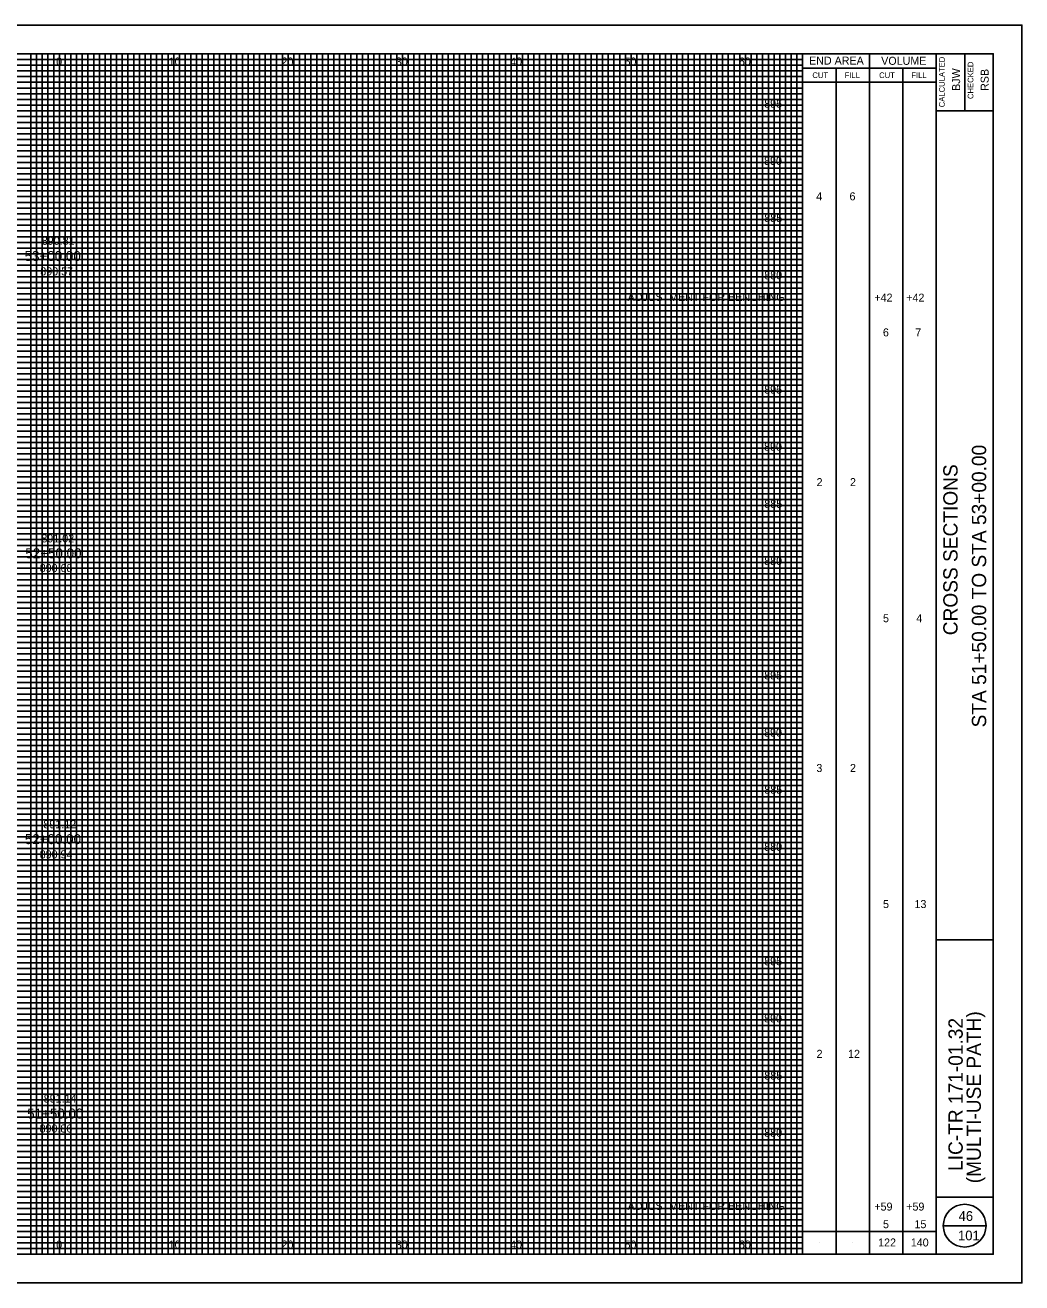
# Model space of a CAD drawing. Extents: x -10 to 160, y -2 to 2522.
# Drawn here: x 72.8 to 160, y 2067.5 to 2177.5 of the extents above; entities that cross this region are included whole.
import ezdxf

# ---------------------------------------------------------------- set-up
doc = ezdxf.new("R2010")
doc.units = 0
for name, color, linetype in [('GK_Cells', 7, 'Continuous'), ('GK_Patterns', 7, 'Continuous'), ('TX_P_10', 7, 'Continuous'), ('TX_X_10', 7, 'Continuous'), ('XS_P_Finished_Grade_Seeded', 7, 'Continuous'), ('XS_P_Pavt_Surface', 7, 'Continuous'), ('XS_P_Subgrade', 7, 'Continuous'), ('XS_X_Ground_Line', 7, 'Continuous')]:
    doc.layers.add(name, color=color, linetype=linetype)

msp = doc.modelspace()

# ---------------------------------------------------------------- linework, layer by layer
at = {"layer": 'GK_Cells'}
msp.add_lwpolyline([(-10, 2067.5), (160, 2067.5), (160, 2177.5), (-10, 2177.5)], close=True, dxfattribs=at)
at = {"layer": 'TX_P_10'}
for p, q in [((140.83, 2070), (140.83, 2175)), ((146.67, 2070), (146.67, 2175)), ((140.83, 2173.75), (152.5, 2173.75)), ((143.75, 2070), (143.75, 2173.75)), ((149.58, 2070), (149.58, 2173.75)), ((140.83, 2172.5), (152.5, 2172.5)), ((153.12, 2072.5), (156.88, 2072.5)), ((140.83, 2072), (152.5, 2072)), ((142.29, 2071), (142.29, 2071)), ((145.21, 2071), (145.21, 2071)), ((148.12, 2071), (148.12, 2071)), ((151.04, 2071), (151.04, 2071))]:
    msp.add_line(p, q, dxfattribs=at)
msp.add_circle((155, 2072.5), 1.87, dxfattribs=at)
at = {"layer": 'TX_X_10'}
for p, q in [((75.83, 2070), (75.83, 2175)), ((80.83, 2070), (80.83, 2175)), ((85.83, 2070), (85.83, 2175)), ((90.83, 2070), (90.83, 2175)), ((95.83, 2070), (95.83, 2175)), ((100.83, 2070), (100.83, 2175)), ((105.83, 2070), (105.83, 2175)), ((110.83, 2070), (110.83, 2175)), ((115.83, 2070), (115.83, 2175)), ((120.83, 2070), (120.83, 2175)), ((125.83, 2070), (125.83, 2175)), ((130.83, 2070), (130.83, 2175)), ((135.83, 2070), (135.83, 2175)), ((5.83, 2170), (140.83, 2170)), ((5.83, 2165), (140.83, 2165)), ((5.83, 2160), (140.83, 2160)), ((5.83, 2155), (140.83, 2155)), ((5.83, 2150), (140.83, 2150)), ((5.83, 2145), (140.83, 2145)), ((5.83, 2140), (140.83, 2140)), ((5.83, 2135), (140.83, 2135)), ((5.83, 2130), (140.83, 2130)), ((5.83, 2125), (140.83, 2125)), ((5.83, 2120), (140.83, 2120)), ((5.83, 2115), (140.83, 2115)), ((5.83, 2110), (140.83, 2110)), ((5.83, 2105), (140.83, 2105)), ((5.83, 2100), (140.83, 2100)), ((5.83, 2095), (140.83, 2095)), ((5.83, 2090), (140.83, 2090)), ((5.83, 2085), (140.83, 2085)), ((5.83, 2080), (140.83, 2080)), ((5.83, 2075), (140.83, 2075))]:
    msp.add_line(p, q, dxfattribs=at)
at = {"layer": 'XS_P_Pavt_Surface'}
for p, q in [((152.5, 2070), (152.5, 2175)), ((155, 2175), (155, 2170)), ((152.5, 2170), (157.5, 2170)), ((152.5, 2097.5), (157.5, 2097.5)), ((152.5, 2075), (157.5, 2075))]:
    msp.add_line(p, q, dxfattribs=at)
msp.add_lwpolyline([(0, 2175), (157.5, 2175), (157.5, 2070), (0, 2070)], close=True, dxfattribs=at)
at = {"layer": 'XS_X_Ground_Line'}
for p, q in [((73.33, 2070), (73.33, 2175)), ((73.83, 2070), (73.83, 2175)), ((74.33, 2070), (74.33, 2175)), ((74.83, 2070), (74.83, 2175)), ((75.33, 2070), (75.33, 2175)), ((76.33, 2070), (76.33, 2175)), ((76.83, 2070), (76.83, 2175)), ((77.33, 2070), (77.33, 2175)), ((77.83, 2070), (77.83, 2175)), ((78.33, 2070), (78.33, 2175)), ((78.83, 2070), (78.83, 2175)), ((79.33, 2070), (79.33, 2175)), ((79.83, 2070), (79.83, 2175)), ((80.33, 2070), (80.33, 2175)), ((81.33, 2070), (81.33, 2175)), ((81.83, 2070), (81.83, 2175)), ((82.33, 2070), (82.33, 2175)), ((82.83, 2070), (82.83, 2175)), ((83.33, 2070), (83.33, 2175)), ((83.83, 2070), (83.83, 2175)), ((84.33, 2070), (84.33, 2175)), ((84.83, 2070), (84.83, 2175)), ((85.33, 2070), (85.33, 2175)), ((86.33, 2070), (86.33, 2175)), ((86.83, 2070), (86.83, 2175)), ((87.33, 2070), (87.33, 2175)), ((87.83, 2070), (87.83, 2175)), ((88.33, 2070), (88.33, 2175)), ((88.83, 2070), (88.83, 2175)), ((89.33, 2070), (89.33, 2175)), ((89.83, 2070), (89.83, 2175)), ((90.33, 2070), (90.33, 2175)), ((91.33, 2070), (91.33, 2175)), ((91.83, 2070), (91.83, 2175)), ((92.33, 2070), (92.33, 2175)), ((92.83, 2070), (92.83, 2175)), ((93.33, 2070), (93.33, 2175)), ((93.83, 2070), (93.83, 2175)), ((94.33, 2070), (94.33, 2175)), ((94.83, 2070), (94.83, 2175)), ((95.33, 2070), (95.33, 2175)), ((96.33, 2070), (96.33, 2175)), ((96.83, 2070), (96.83, 2175)), ((97.33, 2070), (97.33, 2175)), ((97.83, 2070), (97.83, 2175)), ((98.33, 2070), (98.33, 2175)), ((98.83, 2070), (98.83, 2175)), ((99.33, 2070), (99.33, 2175)), ((99.83, 2070), (99.83, 2175)), ((100.33, 2070), (100.33, 2175)), ((101.33, 2070), (101.33, 2175)), ((101.83, 2070), (101.83, 2175)), ((102.33, 2070), (102.33, 2175)), ((102.83, 2070), (102.83, 2175)), ((103.33, 2070), (103.33, 2175)), ((103.83, 2070), (103.83, 2175)), ((104.33, 2070), (104.33, 2175)), ((104.83, 2070), (104.83, 2175)), ((105.33, 2070), (105.33, 2175)), ((106.33, 2070), (106.33, 2175)), ((106.83, 2070), (106.83, 2175)), ((107.33, 2070), (107.33, 2175)), ((107.83, 2070), (107.83, 2175)), ((108.33, 2070), (108.33, 2175)), ((108.83, 2070), (108.83, 2175)), ((109.33, 2070), (109.33, 2175)), ((109.83, 2070), (109.83, 2175)), ((110.33, 2070), (110.33, 2175)), ((111.33, 2070), (111.33, 2175)), ((111.83, 2070), (111.83, 2175)), ((112.33, 2070), (112.33, 2175)), ((112.83, 2070), (112.83, 2175)), ((113.33, 2070), (113.33, 2175)), ((113.83, 2070), (113.83, 2175)), ((114.33, 2070), (114.33, 2175)), ((114.83, 2070), (114.83, 2175)), ((115.33, 2070), (115.33, 2175)), ((116.33, 2070), (116.33, 2175)), ((116.83, 2070), (116.83, 2175)), ((117.33, 2070), (117.33, 2175)), ((117.83, 2070), (117.83, 2175)), ((118.33, 2070), (118.33, 2175)), ((118.83, 2070), (118.83, 2175)), ((119.33, 2070), (119.33, 2175)), ((119.83, 2070), (119.83, 2175)), ((120.33, 2070), (120.33, 2175)), ((121.33, 2070), (121.33, 2175)), ((121.83, 2070), (121.83, 2175)), ((122.33, 2070), (122.33, 2175)), ((122.83, 2070), (122.83, 2175)), ((123.33, 2070), (123.33, 2175)), ((123.83, 2070), (123.83, 2175)), ((124.33, 2070), (124.33, 2175)), ((124.83, 2070), (124.83, 2175)), ((125.33, 2070), (125.33, 2175)), ((126.33, 2070), (126.33, 2175)), ((126.83, 2070), (126.83, 2175)), ((127.33, 2070), (127.33, 2175)), ((127.83, 2070), (127.83, 2175)), ((128.33, 2070), (128.33, 2175)), ((128.83, 2070), (128.83, 2175)), ((129.33, 2070), (129.33, 2175)), ((129.83, 2070), (129.83, 2175)), ((130.33, 2070), (130.33, 2175)), ((131.33, 2070), (131.33, 2175)), ((131.83, 2070), (131.83, 2175)), ((132.33, 2070), (132.33, 2175)), ((132.83, 2070), (132.83, 2175)), ((133.33, 2070), (133.33, 2175)), ((133.83, 2070), (133.83, 2175)), ((134.33, 2070), (134.33, 2175)), ((134.83, 2070), (134.83, 2175)), ((135.33, 2070), (135.33, 2175)), ((136.33, 2070), (136.33, 2175)), ((136.83, 2070), (136.83, 2175)), ((137.33, 2070), (137.33, 2175)), ((137.83, 2070), (137.83, 2175)), ((138.33, 2070), (138.33, 2175)), ((138.83, 2070), (138.83, 2175)), ((139.33, 2070), (139.33, 2175)), ((139.83, 2070), (139.83, 2175)), ((140.33, 2070), (140.33, 2175)), ((5.83, 2174.5), (140.83, 2174.5)), ((5.83, 2174), (140.83, 2174)), ((5.83, 2173.5), (140.83, 2173.5)), ((5.83, 2173), (140.83, 2173)), ((5.83, 2172.5), (140.83, 2172.5)), ((5.83, 2172), (140.83, 2172)), ((5.83, 2171.5), (140.83, 2171.5)), ((5.83, 2171), (140.83, 2171)), ((5.83, 2170.5), (140.83, 2170.5)), ((5.83, 2169.5), (140.83, 2169.5)), ((5.83, 2169), (140.83, 2169)), ((5.83, 2168.5), (140.83, 2168.5)), ((5.83, 2168), (140.83, 2168)), ((5.83, 2167.5), (140.83, 2167.5)), ((5.83, 2167), (140.83, 2167)), ((5.83, 2166.5), (140.83, 2166.5)), ((5.83, 2166), (140.83, 2166)), ((5.83, 2165.5), (140.83, 2165.5)), ((5.83, 2164.5), (140.83, 2164.5)), ((5.83, 2164), (140.83, 2164)), ((5.83, 2163.5), (140.83, 2163.5)), ((5.83, 2163), (140.83, 2163)), ((5.83, 2162.5), (140.83, 2162.5)), ((5.83, 2162), (140.83, 2162)), ((5.83, 2161.5), (140.83, 2161.5)), ((5.83, 2161), (140.83, 2161)), ((5.83, 2160.5), (140.83, 2160.5)), ((5.83, 2159.5), (140.83, 2159.5)), ((5.83, 2159), (140.83, 2159)), ((5.83, 2158.5), (140.83, 2158.5)), ((5.83, 2158), (140.83, 2158)), ((5.83, 2157.5), (140.83, 2157.5)), ((5.83, 2157), (140.83, 2157)), ((5.83, 2156.5), (140.83, 2156.5)), ((5.83, 2156), (140.83, 2156)), ((5.83, 2155.5), (140.83, 2155.5)), ((5.83, 2154.5), (140.83, 2154.5)), ((5.83, 2154), (140.83, 2154)), ((5.83, 2153.5), (140.83, 2153.5)), ((5.83, 2153), (140.83, 2153)), ((5.83, 2152.5), (140.83, 2152.5)), ((5.83, 2152), (140.83, 2152)), ((5.83, 2151.5), (140.83, 2151.5)), ((5.83, 2151), (140.83, 2151)), ((5.83, 2150.5), (140.83, 2150.5)), ((5.83, 2149.5), (140.83, 2149.5)), ((5.83, 2149), (140.83, 2149)), ((5.83, 2148.5), (140.83, 2148.5)), ((5.83, 2148), (140.83, 2148)), ((5.83, 2147.5), (140.83, 2147.5)), ((5.83, 2147), (140.83, 2147)), ((5.83, 2146.5), (140.83, 2146.5)), ((5.83, 2146), (140.83, 2146)), ((5.83, 2145.5), (140.83, 2145.5)), ((5.83, 2144.5), (140.83, 2144.5)), ((5.83, 2144), (140.83, 2144)), ((5.83, 2143.5), (140.83, 2143.5)), ((5.83, 2143), (140.83, 2143)), ((5.83, 2142.5), (140.83, 2142.5)), ((5.83, 2142), (140.83, 2142)), ((5.83, 2141.5), (140.83, 2141.5)), ((5.83, 2141), (140.83, 2141)), ((5.83, 2140.5), (140.83, 2140.5)), ((5.83, 2139.5), (140.83, 2139.5)), ((5.83, 2139), (140.83, 2139)), ((5.83, 2138.5), (140.83, 2138.5)), ((5.83, 2138), (140.83, 2138)), ((5.83, 2137.5), (140.83, 2137.5)), ((5.83, 2137), (140.83, 2137)), ((5.83, 2136.5), (140.83, 2136.5)), ((5.83, 2136), (140.83, 2136)), ((5.83, 2135.5), (140.83, 2135.5)), ((5.83, 2134.5), (140.83, 2134.5)), ((5.83, 2134), (140.83, 2134)), ((5.83, 2133.5), (140.83, 2133.5)), ((5.83, 2133), (140.83, 2133)), ((5.83, 2132.5), (140.83, 2132.5)), ((5.83, 2132), (140.83, 2132)), ((5.83, 2131.5), (140.83, 2131.5)), ((5.83, 2131), (140.83, 2131)), ((5.83, 2130.5), (140.83, 2130.5)), ((5.83, 2129.5), (140.83, 2129.5)), ((5.83, 2129), (140.83, 2129)), ((5.83, 2128.5), (140.83, 2128.5)), ((5.83, 2128), (140.83, 2128)), ((5.83, 2127.5), (140.83, 2127.5)), ((5.83, 2127), (140.83, 2127)), ((5.83, 2126.5), (140.83, 2126.5)), ((5.83, 2126), (140.83, 2126)), ((5.83, 2125.5), (140.83, 2125.5)), ((5.83, 2124.5), (140.83, 2124.5)), ((5.83, 2124), (140.83, 2124)), ((5.83, 2123.5), (140.83, 2123.5)), ((5.83, 2123), (140.83, 2123)), ((5.83, 2122.5), (140.83, 2122.5)), ((5.83, 2122), (140.83, 2122)), ((5.83, 2121.5), (140.83, 2121.5)), ((5.83, 2121), (140.83, 2121)), ((5.83, 2120.5), (140.83, 2120.5)), ((5.83, 2119.5), (140.83, 2119.5)), ((5.83, 2119), (140.83, 2119)), ((5.83, 2118.5), (140.83, 2118.5)), ((5.83, 2118), (140.83, 2118)), ((5.83, 2117.5), (140.83, 2117.5)), ((5.83, 2117), (140.83, 2117)), ((5.83, 2116.5), (140.83, 2116.5)), ((5.83, 2116), (140.83, 2116)), ((5.83, 2115.5), (140.83, 2115.5)), ((5.83, 2114.5), (140.83, 2114.5)), ((5.83, 2114), (140.83, 2114)), ((5.83, 2113.5), (140.83, 2113.5)), ((5.83, 2113), (140.83, 2113)), ((5.83, 2112.5), (140.83, 2112.5)), ((5.83, 2112), (140.83, 2112)), ((5.83, 2111.5), (140.83, 2111.5)), ((5.83, 2111), (140.83, 2111)), ((5.83, 2110.5), (140.83, 2110.5)), ((5.83, 2109.5), (140.83, 2109.5)), ((5.83, 2109), (140.83, 2109)), ((5.83, 2108.5), (140.83, 2108.5)), ((5.83, 2108), (140.83, 2108)), ((5.83, 2107.5), (140.83, 2107.5)), ((5.83, 2107), (140.83, 2107)), ((5.83, 2106.5), (140.83, 2106.5)), ((5.83, 2106), (140.83, 2106)), ((5.83, 2105.5), (140.83, 2105.5)), ((5.83, 2104.5), (140.83, 2104.5)), ((5.83, 2104), (140.83, 2104)), ((5.83, 2103.5), (140.83, 2103.5)), ((5.83, 2103), (140.83, 2103)), ((5.83, 2102.5), (140.83, 2102.5)), ((5.83, 2102), (140.83, 2102)), ((5.83, 2101.5), (140.83, 2101.5)), ((5.83, 2101), (140.83, 2101)), ((5.83, 2100.5), (140.83, 2100.5)), ((5.83, 2099.5), (140.83, 2099.5)), ((5.83, 2099), (140.83, 2099)), ((5.83, 2098.5), (140.83, 2098.5)), ((5.83, 2098), (140.83, 2098)), ((5.83, 2097.5), (140.83, 2097.5)), ((5.83, 2097), (140.83, 2097)), ((5.83, 2096.5), (140.83, 2096.5)), ((5.83, 2096), (140.83, 2096)), ((5.83, 2095.5), (140.83, 2095.5)), ((5.83, 2094.5), (140.83, 2094.5)), ((5.83, 2094), (140.83, 2094)), ((5.83, 2093.5), (140.83, 2093.5)), ((5.83, 2093), (140.83, 2093)), ((5.83, 2092.5), (140.83, 2092.5)), ((5.83, 2092), (140.83, 2092)), ((5.83, 2091.5), (140.83, 2091.5)), ((5.83, 2091), (140.83, 2091)), ((5.83, 2090.5), (140.83, 2090.5)), ((5.83, 2089.5), (140.83, 2089.5)), ((5.83, 2089), (140.83, 2089)), ((5.83, 2088.5), (140.83, 2088.5)), ((5.83, 2088), (140.83, 2088)), ((5.83, 2087.5), (140.83, 2087.5)), ((5.83, 2087), (140.83, 2087)), ((5.83, 2086.5), (140.83, 2086.5)), ((5.83, 2086), (140.83, 2086)), ((5.83, 2085.5), (140.83, 2085.5)), ((5.83, 2084.5), (140.83, 2084.5)), ((5.83, 2084), (140.83, 2084)), ((5.83, 2083.5), (140.83, 2083.5)), ((5.83, 2083), (140.83, 2083)), ((5.83, 2082.5), (140.83, 2082.5)), ((5.83, 2082), (140.83, 2082)), ((5.83, 2081.5), (140.83, 2081.5)), ((5.83, 2081), (140.83, 2081)), ((5.83, 2080.5), (140.83, 2080.5)), ((5.83, 2079.5), (140.83, 2079.5)), ((5.83, 2079), (140.83, 2079)), ((5.83, 2078.5), (140.83, 2078.5)), ((5.83, 2078), (140.83, 2078)), ((5.83, 2077.5), (140.83, 2077.5)), ((5.83, 2077), (140.83, 2077)), ((5.83, 2076.5), (140.83, 2076.5)), ((5.83, 2076), (140.83, 2076)), ((5.83, 2075.5), (140.83, 2075.5)), ((5.83, 2074.5), (140.83, 2074.5)), ((5.83, 2074), (140.83, 2074)), ((5.83, 2073.5), (140.83, 2073.5)), ((5.83, 2073), (140.83, 2073)), ((5.83, 2072.5), (140.83, 2072.5)), ((5.83, 2072), (140.83, 2072)), ((5.83, 2071.5), (140.83, 2071.5)), ((5.83, 2071), (140.83, 2071)), ((5.83, 2070.5), (140.83, 2070.5))]:
    msp.add_line(p, q, dxfattribs=at)

# ---------------------------------------------------------------- texts
at = {"layer": 'GK_Patterns'}
for s, height, p in [('0', 0.7, (75.55, 2173.97)), ('0', 0.7, (75.55, 2173.97)), ('10', 0.7, (85.39, 2173.97)), ('20', 0.7, (95.26, 2173.97)), ('30', 0.7, (105.25, 2173.97)), ('40', 0.7, (115.25, 2173.97)), ('50', 0.7, (125.25, 2173.97)), ('60', 0.7, (135.25, 2173.97)), ('895', 0.7, (137.47, 2170.28)), ('890', 0.7, (137.46, 2165.28)), ('4', 0.7, (142.02, 2162.18)), ('6', 0.7, (144.93, 2162.18)), ('885', 0.7, (137.48, 2160.28)), ('53+00.00', 0.875, (72.79, 2156.87)), ('880', 0.7, (137.47, 2155.28)), ('ADJUSTMENT FOR BENCHING', 0.7, (125.52, 2153.37)), ('+42', 0.7, (147.1, 2153.32)), ('+42', 0.7, (149.89, 2153.32)), ('6', 0.7, (147.85, 2150.28)), ('7', 0.7, (150.68, 2150.28)), ('895', 0.7, (137.47, 2145.28)), ('890', 0.7, (137.46, 2140.28)), ('2', 0.7, (142.05, 2137.18)), ('2', 0.7, (144.97, 2137.18)), ('885', 0.7, (137.48, 2135.28)), ('52+50.00', 0.875, (72.85, 2130.87)), ('880', 0.7, (137.47, 2130.28)), ('5', 0.7, (147.86, 2125.28)), ('4', 0.7, (150.77, 2125.28)), ('895', 0.7, (137.47, 2120.28)), ('890', 0.7, (137.46, 2115.28)), ('3', 0.7, (142.03, 2112.18)), ('2', 0.7, (144.97, 2112.18)), ('885', 0.7, (137.48, 2110.28)), ('52+00.00', 0.875, (72.81, 2105.87)), ('880', 0.7, (137.47, 2105.28)), ('5', 0.7, (147.86, 2100.28)), ('13', 0.7, (150.61, 2100.28)), ('895', 0.7, (137.47, 2095.28)), ('890', 0.7, (137.46, 2090.28)), ('2', 0.7, (142.05, 2087.18)), ('12', 0.7, (144.8, 2087.18)), ('885', 0.7, (137.48, 2085.28)), ('51+50.00', 0.875, (73.01, 2081.87)), ('880', 0.7, (137.47, 2080.28)), ('ADJUSTMENT FOR BENCHING', 0.7, (125.52, 2073.87)), ('+59', 0.7, (147.1, 2073.82)), ('+59', 0.7, (149.89, 2073.82)), ('5', 0.7, (147.86, 2072.28)), ('15', 0.7, (150.61, 2072.28)), ('122', 0.7, (147.43, 2070.68)), ('140', 0.7, (150.29, 2070.68)), ('0', 0.7, (75.55, 2070.5)), ('0', 0.7, (75.55, 2070.5)), ('10', 0.7, (85.39, 2070.5)), ('20', 0.7, (95.26, 2070.5)), ('30', 0.7, (105.25, 2070.5)), ('40', 0.7, (115.25, 2070.5)), ('50', 0.7, (125.25, 2070.5)), ('60', 0.7, (135.25, 2070.5))]:
    msp.add_text(s, height=height, dxfattribs=at).set_placement(p)
at = {"layer": 'TX_P_10'}
for s, height, p in [('END AREA', 0.7, (141.39, 2174.05)), ('VOLUME', 0.7, (147.7, 2174.03)), ('CUT', 0.5, (141.68, 2172.87)), ('FILL', 0.5, (144.5, 2172.87)), ('CUT', 0.5, (147.52, 2172.87)), ('FILL', 0.5, (150.34, 2172.87)), ('46', 0.85, (154.47, 2072.92)), ('101', 0.85, (154.42, 2071.22))]:
    msp.add_text(s, height=height, dxfattribs=at).set_placement(p)
for s, height, p in [('CALCULATED', 0.5, (153.26, 2170.32)), ('BJW', 0.7, (154.6, 2171.75)), ('CHECKED', 0.5, (155.76, 2171.04)), ('RSB', 0.7, (157.1, 2171.75)), ('STA 51+50.00 TO STA 53+00.00', 1.25, (156.88, 2116.08)), ('CROSS SECTIONS', 1.25, (154.38, 2124.14)), ('(MULTI-USE PATH)', 1.25, (156.42, 2076.21)), ('LIC-TR 171-01.32', 1.25, (154.83, 2077.29))]:
    msp.add_text(s, height=height, rotation=90, dxfattribs=at).set_placement(p)
at = {"layer": 'XS_P_Finished_Grade_Seeded'}
for s, p in [('890.57', (74.16, 2155.62)), ('890.68', (74.11, 2129.67)), ('890.94', (74.11, 2104.63)), ('890.86', (74.1, 2080.65))]:
    msp.add_text(s, height=0.7, dxfattribs=at).set_placement(p)
at = {"layer": 'XS_P_Subgrade'}
for s, p in [('890.81', (74.29, 2158.29)), ('891.02', (74.26, 2132.26)), ('891.12', (74.43, 2107.26)), ('891.14', (74.46, 2083.27))]:
    msp.add_text(s, height=0.7, dxfattribs=at).set_placement(p)

doc.saveas('drawing.dxf')
